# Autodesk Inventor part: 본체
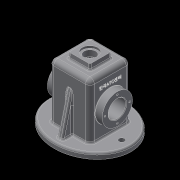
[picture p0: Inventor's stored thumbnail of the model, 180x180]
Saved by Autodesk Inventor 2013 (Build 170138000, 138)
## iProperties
Created: 2017-07
Part Number: 본체
Material: 일반
Document SubType Name: Modeling
Designer: elite
Density: 1 g/cm^3
Author: elite
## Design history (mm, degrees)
sketch "스케치1"
  geometry: L1 (-37, 37)-(37, 37); L2 (37, 37)-(37, -37); L3 (37, -37)-(-37, -37); L4 (-37, -37)-(-37, 37); 3 further points
  constraints: 8 end point, 2 midpoint, 2 parallel, 1 horizontal, 1 horizontal alignment, 1 perpendicular, 1 vertical alignment
  dimensions: "d0" = 74 distance of L1.start L1.end; "d2" = 74 distance between parallel lines of L3 L1
extrude "돌출1" new body sketch "스케치1" distance "d3" = 110; taper "d4" = 0 deg
feature "쉘1" dims "d5" = 5
sketch "스케치2" dims "d6" = 65, "d8" = 75
  geometry: L1 (-32, 32)-(32, 32) reference; L2 (37, 37)-(-37, 37) reference; L3 (-37, 37)-(-37, -37) reference; L4 (-37, -37)-(37, -37) reference; L5 (37, -37)-(37, 37) reference; 2 further points; 1 other entity
  constraints: 1 coincident, 1 horizontal, 2 other
extrude "돌출2" join sketch "스케치2" distance "d9" = 10; taper "d10" = 0 deg
node "작업 평면1"
sketch "스케치3"
  geometry: L1 (-5, 69)-(-110, 69) reference; L2 (-110, 69)-(-110, 102) reference; L3 (-110, 102)-(-100, 102) reference; L4 (-100, 102)-(-100, 74) reference; L5 (-100, 74)-(0, 74) reference; L6 (0, 74)-(0, 0) reference; L7 (0, 0)-(-100, 0) reference; L8 (-100, 0)-(-100, -28) reference; L9 (-100, -28)-(-110, -28) reference; L10 (-110, -28)-(-110, 5) reference; L11 (-110, 5)-(-5, 5) reference; L12 (-5, 5)-(-5, 69) reference; L13 (-100, -18)-(-27.806, 0); 1 further point
  constraints: 2 end point, 2 point on line
  dimensions: "d11" = 14 deg angle of L9 L13; "d12" = 10 distance from line of L9 L13.start
extrude "돌출3" join sketch "스케치3" stored distance "d13" = 10; taper "d14" = 0 deg
node "작업 평면2"
sketch "스케치4"
  geometry: L1 (0, 0)-(0, 74) reference; L2 (110, 102)-(110, -28) reference; C1 r 27.5 at (55, 37); 2 further points
  constraints: 1 centre point, 1 horizontal alignment, 1 midpoint
  dimensions: "d15" = 55 diameter of C1; "d17" = 55 distance from line of L2 C1.centre
extrude "돌출4" join sketch "스케치4" distance "d18" = 13; taper "d19" = 0 deg
sketch "스케치5"
  geometry: C1 r 27.5 at (55, 32) reference; C2 r 27.5 at (55, 32); 1 further point
  constraints: 1 centre point, 1 coincident, 1 concentric
  dimensions: "d20" = 55 diameter of C2 (derived)
extrude "돌출5" join sketch "스케치5" distance "d21" = 7; taper "d22" = 0 deg
node "작업 평면3"
sketch "스케치6"
  geometry: L1 (-32, 27.5)-(-25, 27.5) reference; L2 (-25, 27.5)-(-25, -27.5) reference; L3 (-25, -27.5)-(-32, -27.5) reference; L4 (-32, -27.5)-(-32, -32) reference; L5 (-32, -32)-(32, -32) reference; L6 (32, -32)-(32, 32) reference; L7 (32, 32)-(-32, 32) reference; L8 (-32, 32)-(-32, 27.5) reference; L9 (-5, -43.78)-(-5, -37) reference; L10 (-5, -37)-(-37, -37) reference; L11 (-37, -37)-(-37, -27.5) reference; L12 (-37, -27.5)-(-50, -27.5) reference; L13 (-50, -27.5)-(-50, 27.5) reference; L14 (-50, 27.5)-(-37, 27.5) reference; L15 (-37, 27.5)-(-37, 37) reference; L16 (-37, 37)-(-5, 37) reference; L17 (-5, 37)-(-5, 43.78) reference; L18 (-5, 43.78)-(5, 43.78) reference; L19 (5, 43.78)-(5, 37) reference; L20 (5, 37)-(37, 37) reference; L21 (37, 37)-(37, -37) reference; L22 (37, -37)-(5, -37) reference; L23 (5, -37)-(5, -43.78) reference; L24 (5, -43.78)-(-5, -43.78) reference; L25 (-32, 27.5)-(-25, 20.5); L26 (-25, 0)-(-50, 0); 2 further points
  constraints: 4 end point, 3 midpoint, 2 point on line, 1 perpendicular
  dimensions: "d24" = 45 deg angle of L1 L25
revolve "회전1" sketch "스케치6" stored, may be unused: angle "d25" = 90 deg
sketch "스케치7"
  geometry: C1 r 27.5 at (0, 0) reference; 2 further points
  constraints: 1 horizontal alignment
  dimensions: "d26" = 22.5 distance of point (-22.5, 0) C1.centre
hole "구멍1" sketch "스케치7" at (-22.5, 0) diameter "d27" = 3.242; stored, may be unused: countersink angle "d31" = 90 deg, drill point angle "d33" = 118 deg; dims "d28" = 8, "d29" = 4, "d30" = 2, "d32" = 10
hole "구멍2" diameter "d39" = 32; stored, may be unused: countersink angle "d43" = 90 deg, drill point angle "d45" = 0 deg; dims "d37" = 10, "d38" = 10, "d40" = 8, "d41" = 4, "d42" = 2, "d44" = 10
sketch "스케치8"
  geometry: L1 (-5, 37)-(-37, 37) reference; L2 (0, 65)-(0, -65); C1 r 5 at (-58, 0); C2 r 5 at (58, 0); 2 further points; 1 other entity
  constraints: 2 centre point, 2 end point, 2 horizontal alignment, 2 midpoint, 1 equal radius, 1 perpendicular, 3 other
  dimensions: "d49" = 10 diameter of C1; "d50" = 58 distance from line of C1.centre L2; "d51" = 116 distance of C2.centre C1.centre; "d52" = 10 diameter of C2 (derived)
extrude "돌출6" cut sketch "스케치8" stored distance "d53" = 0; taper "d54" = 0 deg
sketch "스케치9"
  geometry: L1 (37, 37)-(-37, 37) reference; L2 (-37, 37)-(-37, -37) reference; L3 (-37, -37)-(37, -37) reference; L4 (37, -37)-(37, 37) reference; L5 (-20, 20)-(20, 20); L6 (20, 20)-(20, -20); L7 (20, -20)-(-20, -20); L8 (-20, -20)-(-20, 20); 1 further point
  constraints: 8 end point, 3 other
  dimensions: "d55" = 40 distance of L5.start L5.end
extrude "돌출7" join sketch "스케치9" distance "d57" = 10; taper "d58" = 0 deg
sketch "스케치10"
  geometry: L1 (0, 10)-(40, 10) reference; L2 (0, 0)-(0, 10) reference; L3 (0, 0)-(0.875, 10); 1 further point
  constraints: 2 end point, 1 point on line
  dimensions: "d59" = 5 deg angle of L2 L3
extrude "돌출8" cut sketch "스케치10" stored distance "d60" = 10; taper "d61" = 0 deg
sketch "스케치11"
  geometry: L1 (-10, 0)-(-10, 40) reference; L2 (0, 0)-(-10, 0) reference; L3 (0, 0)-(-10, 0.875); 1 further point
  constraints: 2 end point, 1 point on line
  dimensions: "d62" = 5 deg angle of L2 L3
extrude "돌출9" cut sketch "스케치11" stored distance "d63" = 10; taper "d64" = 0 deg
sketch "스케치12"
  geometry: 2 further points
  constraints: 1 coincident
hole "구멍3" sketch "스케치12" at (0, 0) diameter "d65" = 21; stored, may be unused: countersink angle "d69" = 90 deg, drill point angle "d71" = 0 deg; dims "d66" = 8, "d67" = 28, "d68" = 4, "d70" = 10
sketch "스케치13"
  geometry: L1 (100, 74)-(0, 74) reference; L2 (-10, 17.875)-(-10, 56.125) reference; 2 further points
  constraints: 1 other
  dimensions: "d72" = 30 distance from line of L2 point (20, 37); "d73" = 37 distance from line of point (20, 37) L1
feature "엠보싱1" sketch "스케치13" dims "d74" = 0.5, "d75" = 0
fillet "모깎기1" dims "d76" = 3
fillet "모깎기2" dims "d77" = 3
fillet "모깎기3" dims "d78" = 3
fillet "모깎기4" dims "d79" = 3
fillet "모깎기5" dims "d80" = 0.5
fillet "모깎기6" dims "d81" = 0.5
fillet "모깎기7" dims "d82" = 8
fillet "모깎기8" dims "d83" = 3
fillet "모깎기9" dims "d84" = 3
fillet "모깎기10" dims "d85" = 8
fillet "모깎기11" dims "d86" = 3
fillet "모깎기12" dims "d87" = 3
chamfer "모따기1" distance "d88" = 1; stored, may be unused: second distance "d89" = 2, angle "d90" = 45 deg
fillet "모깎기13" dims "d91" = 3
fillet "모깎기14" dims "d92" = 3
node "솔리드1"
mirror "대칭1"
pattern_circular "원형 패턴1" dims angle "d35" = 360 deg
mirror "대칭2"
mirror "대칭3"
mirror "대칭4"
node "투영된 루프1"
node "절단 모서리 투영1"
node "절단 모서리 투영2"
other parameters: "d23" = -55
